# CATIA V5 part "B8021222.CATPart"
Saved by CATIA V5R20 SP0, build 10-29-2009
Part number: B8021222
Revision: 17
Definition: design
Nomenclature: B8021222
Source: made
Description: NOT SPECIFIED
Bounding box of the stored display mesh (mm): x -14 to 14, y -14 to 14, z -8 to 22
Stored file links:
  C:\Users\Utente\Desktop\3D files B802\B8021222.CATPart
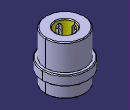
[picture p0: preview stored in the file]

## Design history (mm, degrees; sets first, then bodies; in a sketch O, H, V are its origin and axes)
Body1 "MANIFOLD_SOLID_BREP #38" (main body)
  Solid1: solid without history
Body2 "MANIFOLD_SOLID_BREP #76"
  Solid2: solid without history
Body3 "MANIFOLD_SOLID_BREP #114"
  Solid3: solid without history
Body4 "MANIFOLD_SOLID_BREP #152"
  Solid4: solid without history
Body5 "MANIFOLD_SOLID_BREP #190"
  Solid5: solid without history
Body6 "MANIFOLD_SOLID_BREP #228"
  Solid6: solid without history
Body7 "MANIFOLD_SOLID_BREP #266"
  Solid7: solid without history
Body8 "MANIFOLD_SOLID_BREP #304"
  Solid8: solid without history
Body9 "MANIFOLD_SOLID_BREP #1808"
  Solid9: solid without history
Body10 "MANIFOLD_SOLID_BREP #1846"
  Solid10: solid without history
Body11 "MANIFOLD_SOLID_BREP #1884"
  Solid11: solid without history
Body12 "MANIFOLD_SOLID_BREP #1922"
  Solid12: solid without history
Body13 "MANIFOLD_SOLID_BREP #1960"
  Solid13: solid without history
Body14 "MANIFOLD_SOLID_BREP #1998"
  Solid14: solid without history
Body15 "MANIFOLD_SOLID_BREP #2036"
  Solid15: solid without history
Body16 "MANIFOLD_SOLID_BREP #2074"
  Solid16: solid without history
Body17 "MANIFOLD_SOLID_BREP #2112"
  Solid17: solid without history
Body18 "MANIFOLD_SOLID_BREP #2150"
  Solid18: solid without history
Body19 "MANIFOLD_SOLID_BREP #2188"
  Solid19: solid without history
Body20 "MANIFOLD_SOLID_BREP #2226"
  Solid20: solid without history
Body21 "MANIFOLD_SOLID_BREP #2264"
  Solid21: solid without history
Body22 "MANIFOLD_SOLID_BREP #2302"
  Solid22: solid without history
Body23 "MANIFOLD_SOLID_BREP #2340"
  Solid23: solid without history
Body24 "MANIFOLD_SOLID_BREP #2378"
  Solid24: solid without history
Body25 "MANIFOLD_SOLID_BREP #2416"
  Solid25: solid without history
Body26 "MANIFOLD_SOLID_BREP #2454"
  Solid26: solid without history
Body27 "MANIFOLD_SOLID_BREP #2492"
  Solid27: solid without history
Body28 "MANIFOLD_SOLID_BREP #2530"
  Solid28: solid without history
Body29 "MANIFOLD_SOLID_BREP #2568"
  Solid29: solid without history
Body30 "MANIFOLD_SOLID_BREP #2606"
  Solid30: solid without history
Body31 "MANIFOLD_SOLID_BREP #2644"
  Solid31: solid without history
Body32 "MANIFOLD_SOLID_BREP #2682"
  Solid32: solid without history
Body33 "MANIFOLD_SOLID_BREP #2720"
  Solid33: solid without history
Body34 "MANIFOLD_SOLID_BREP #2758"
  Solid34: solid without history
Body35 "MANIFOLD_SOLID_BREP #2796"
  Solid35: solid without history
Body36 "MANIFOLD_SOLID_BREP #2834"
  Solid36: solid without history
Body37 "MANIFOLD_SOLID_BREP #2872"
  Solid37: solid without history
Body38 "MANIFOLD_SOLID_BREP #2910"
  Solid38: solid without history
Body39 "MANIFOLD_SOLID_BREP #2948"
  Solid39: solid without history
Body40 "MANIFOLD_SOLID_BREP #2986"
  Solid40: solid without history
Body41 "MANIFOLD_SOLID_BREP #3024"
  Solid41: solid without history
